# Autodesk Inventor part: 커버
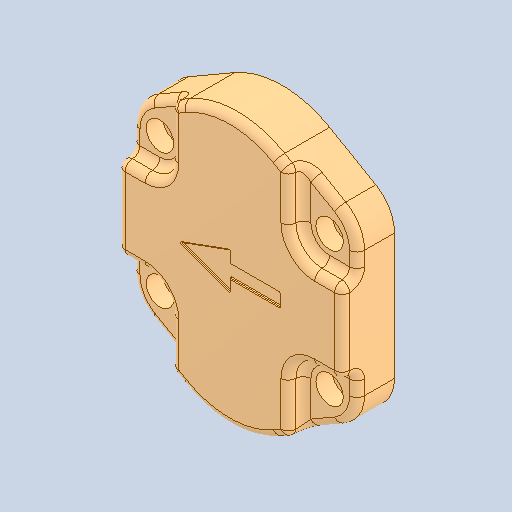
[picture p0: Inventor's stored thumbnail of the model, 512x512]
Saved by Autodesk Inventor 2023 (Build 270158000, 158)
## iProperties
Created: 2025-10
Part Number: 커버
Material: 알루미늄 6061
Document SubType Name: Modeling
Designer: home
Density: 2.7 g/cm^3
Appearance: 기본값
Author: jhkim
Sending System: Autodesk Inventor 2026
Preprocessor: ST-DEVELOPER v20.1
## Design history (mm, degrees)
feature "솔리드2"
node "솔리드1"
